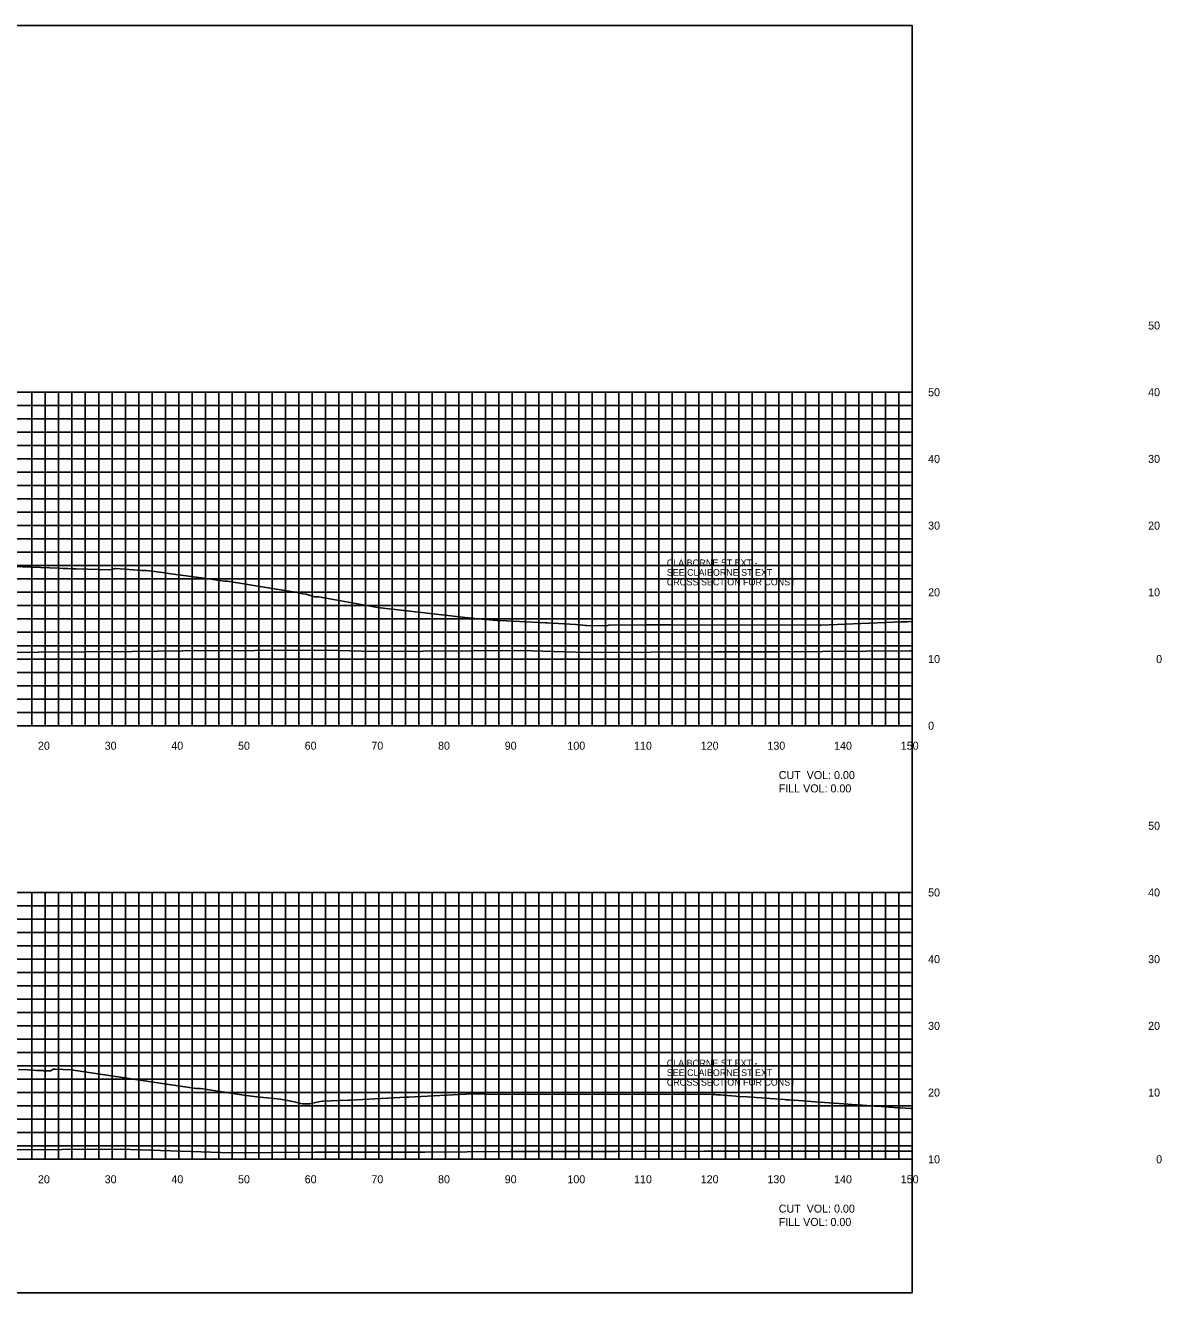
# Model space of a CAD drawing. Extents: x 1797305 to 1804485, y 245831 to 250849.
# Drawn here: x 1803328 to 1803498.4, y 250079.4 to 250269.4 of the extents above; entities that cross this region are included whole.
import ezdxf

# ---------------------------------------------------------------- set-up
doc = ezdxf.new("R2010")
doc.units = 0
for name, color, linetype in [('10', 7, 'Continuous'), ('29', 7, 'Continuous'), ('60', 7, 'Continuous'), ('CL-CNST', 7, 'Continuous'), ('EDPV-LINE', 7, 'Continuous'), ('Level 31', 7, 'Continuous'), ('LIMT-CSLINE', 7, 'Continuous'), ('M-ROADS', 7, 'Continuous')]:
    doc.layers.add(name, color=color, linetype=linetype)

msp = doc.modelspace()

# ---------------------------------------------------------------- linework, layer by layer
msp.add_lwpolyline([(1803161, 250079.43), (1803461, 250079.43), (1803461, 250269.43), (1803161, 250269.43)], close=True)
at = {"layer": '29'}
for p, q in [((1803161, 250214.43), (1803461, 250214.43)), ((1803329, 250164.43), (1803329, 250214.43)), ((1803331, 250164.43), (1803331, 250214.43)), ((1803333, 250164.43), (1803333, 250214.43)), ((1803335, 250164.43), (1803335, 250214.43)), ((1803337, 250164.43), (1803337, 250214.43)), ((1803339, 250164.43), (1803339, 250214.43)), ((1803341, 250164.43), (1803341, 250214.43)), ((1803343, 250164.43), (1803343, 250214.43)), ((1803345, 250164.43), (1803345, 250214.43)), ((1803347, 250164.43), (1803347, 250214.43)), ((1803349, 250164.43), (1803349, 250214.43)), ((1803351, 250164.43), (1803351, 250214.43)), ((1803353, 250164.43), (1803353, 250214.43)), ((1803355, 250164.43), (1803355, 250214.43)), ((1803357, 250164.43), (1803357, 250214.43)), ((1803359, 250164.43), (1803359, 250214.43)), ((1803361, 250164.43), (1803361, 250214.43)), ((1803363, 250164.43), (1803363, 250214.43)), ((1803365, 250164.43), (1803365, 250214.43)), ((1803367, 250164.43), (1803367, 250214.43)), ((1803369, 250164.43), (1803369, 250214.43)), ((1803371, 250164.43), (1803371, 250214.43)), ((1803373, 250164.43), (1803373, 250214.43)), ((1803375, 250164.43), (1803375, 250214.43)), ((1803377, 250164.43), (1803377, 250214.43)), ((1803379, 250164.43), (1803379, 250214.43)), ((1803381, 250164.43), (1803381, 250214.43)), ((1803383, 250164.43), (1803383, 250214.43)), ((1803385, 250164.43), (1803385, 250214.43)), ((1803387, 250164.43), (1803387, 250214.43)), ((1803389, 250164.43), (1803389, 250214.43)), ((1803391, 250164.43), (1803391, 250214.43)), ((1803393, 250164.43), (1803393, 250214.43)), ((1803395, 250164.43), (1803395, 250214.43)), ((1803397, 250164.43), (1803397, 250214.43)), ((1803399, 250164.43), (1803399, 250214.43)), ((1803401, 250164.43), (1803401, 250214.43)), ((1803403, 250164.43), (1803403, 250214.43)), ((1803405, 250164.43), (1803405, 250214.43)), ((1803407, 250164.43), (1803407, 250214.43)), ((1803409, 250164.43), (1803409, 250214.43)), ((1803411, 250164.43), (1803411, 250214.43)), ((1803413, 250164.43), (1803413, 250214.43)), ((1803415, 250164.43), (1803415, 250214.43)), ((1803417, 250164.43), (1803417, 250214.43)), ((1803419, 250164.43), (1803419, 250214.43)), ((1803421, 250164.43), (1803421, 250214.43)), ((1803423, 250164.43), (1803423, 250214.43)), ((1803425, 250164.43), (1803425, 250214.43)), ((1803427, 250164.43), (1803427, 250214.43)), ((1803429, 250164.43), (1803429, 250214.43)), ((1803431, 250164.43), (1803431, 250214.43)), ((1803433, 250164.43), (1803433, 250214.43)), ((1803435, 250164.43), (1803435, 250214.43)), ((1803437, 250164.43), (1803437, 250214.43)), ((1803439, 250164.43), (1803439, 250214.43)), ((1803441, 250164.43), (1803441, 250214.43)), ((1803443, 250164.43), (1803443, 250214.43)), ((1803445, 250164.43), (1803445, 250214.43)), ((1803447, 250164.43), (1803447, 250214.43)), ((1803449, 250164.43), (1803449, 250214.43)), ((1803451, 250164.43), (1803451, 250214.43)), ((1803453, 250164.43), (1803453, 250214.43)), ((1803455, 250164.43), (1803455, 250214.43)), ((1803457, 250164.43), (1803457, 250214.43)), ((1803459, 250164.43), (1803459, 250214.43)), ((1803461, 250164.43), (1803461, 250214.43)), ((1803161, 250212.43), (1803461, 250212.43)), ((1803161, 250210.43), (1803461, 250210.43)), ((1803161, 250208.43), (1803461, 250208.43)), ((1803161, 250206.43), (1803461, 250206.43)), ((1803161, 250204.43), (1803461, 250204.43)), ((1803161, 250202.43), (1803461, 250202.43)), ((1803161, 250200.43), (1803461, 250200.43)), ((1803161, 250198.43), (1803461, 250198.43)), ((1803161, 250196.43), (1803461, 250196.43)), ((1803161, 250194.43), (1803461, 250194.43)), ((1803161, 250192.43), (1803461, 250192.43)), ((1803161, 250190.43), (1803461, 250190.43)), ((1803161, 250188.43), (1803461, 250188.43)), ((1803161, 250186.43), (1803461, 250186.43)), ((1803161, 250184.43), (1803461, 250184.43)), ((1803161, 250182.43), (1803461, 250182.43)), ((1803161, 250180.43), (1803461, 250180.43)), ((1803161, 250178.43), (1803461, 250178.43)), ((1803161, 250176.43), (1803461, 250176.43)), ((1803161, 250174.43), (1803461, 250174.43)), ((1803161, 250172.43), (1803461, 250172.43)), ((1803161, 250170.43), (1803461, 250170.43)), ((1803161, 250168.43), (1803461, 250168.43)), ((1803161, 250166.43), (1803461, 250166.43)), ((1803161, 250164.43), (1803461, 250164.43)), ((1803161, 250139.43), (1803461, 250139.43)), ((1803329, 250099.43), (1803329, 250139.43)), ((1803331, 250099.43), (1803331, 250139.43)), ((1803333, 250099.43), (1803333, 250139.43)), ((1803335, 250099.43), (1803335, 250139.43)), ((1803337, 250099.43), (1803337, 250139.43)), ((1803339, 250099.43), (1803339, 250139.43)), ((1803341, 250099.43), (1803341, 250139.43)), ((1803343, 250099.43), (1803343, 250139.43)), ((1803345, 250099.43), (1803345, 250139.43)), ((1803347, 250099.43), (1803347, 250139.43)), ((1803349, 250099.43), (1803349, 250139.43)), ((1803351, 250099.43), (1803351, 250139.43)), ((1803353, 250099.43), (1803353, 250139.43)), ((1803355, 250099.43), (1803355, 250139.43)), ((1803357, 250099.43), (1803357, 250139.43)), ((1803359, 250099.43), (1803359, 250139.43)), ((1803361, 250099.43), (1803361, 250139.43)), ((1803363, 250099.43), (1803363, 250139.43)), ((1803365, 250099.43), (1803365, 250139.43)), ((1803367, 250099.43), (1803367, 250139.43)), ((1803369, 250099.43), (1803369, 250139.43)), ((1803371, 250099.43), (1803371, 250139.43)), ((1803373, 250099.43), (1803373, 250139.43)), ((1803375, 250099.43), (1803375, 250139.43)), ((1803377, 250099.43), (1803377, 250139.43)), ((1803379, 250099.43), (1803379, 250139.43)), ((1803381, 250099.43), (1803381, 250139.43)), ((1803383, 250099.43), (1803383, 250139.43)), ((1803385, 250099.43), (1803385, 250139.43)), ((1803387, 250099.43), (1803387, 250139.43)), ((1803389, 250099.43), (1803389, 250139.43)), ((1803391, 250099.43), (1803391, 250139.43)), ((1803393, 250099.43), (1803393, 250139.43)), ((1803395, 250099.43), (1803395, 250139.43)), ((1803397, 250099.43), (1803397, 250139.43)), ((1803399, 250099.43), (1803399, 250139.43)), ((1803401, 250099.43), (1803401, 250139.43)), ((1803403, 250099.43), (1803403, 250139.43)), ((1803405, 250099.43), (1803405, 250139.43)), ((1803407, 250099.43), (1803407, 250139.43)), ((1803409, 250099.43), (1803409, 250139.43)), ((1803411, 250099.43), (1803411, 250139.43)), ((1803413, 250099.43), (1803413, 250139.43)), ((1803415, 250099.43), (1803415, 250139.43)), ((1803417, 250099.43), (1803417, 250139.43)), ((1803419, 250099.43), (1803419, 250139.43)), ((1803421, 250099.43), (1803421, 250139.43)), ((1803423, 250099.43), (1803423, 250139.43)), ((1803425, 250099.43), (1803425, 250139.43)), ((1803427, 250099.43), (1803427, 250139.43)), ((1803429, 250099.43), (1803429, 250139.43)), ((1803431, 250099.43), (1803431, 250139.43)), ((1803433, 250099.43), (1803433, 250139.43)), ((1803435, 250099.43), (1803435, 250139.43)), ((1803437, 250099.43), (1803437, 250139.43)), ((1803439, 250099.43), (1803439, 250139.43)), ((1803441, 250099.43), (1803441, 250139.43)), ((1803443, 250099.43), (1803443, 250139.43)), ((1803445, 250099.43), (1803445, 250139.43)), ((1803447, 250099.43), (1803447, 250139.43)), ((1803449, 250099.43), (1803449, 250139.43)), ((1803451, 250099.43), (1803451, 250139.43)), ((1803453, 250099.43), (1803453, 250139.43)), ((1803455, 250099.43), (1803455, 250139.43)), ((1803457, 250099.43), (1803457, 250139.43)), ((1803459, 250099.43), (1803459, 250139.43)), ((1803461, 250099.43), (1803461, 250139.43)), ((1803161, 250137.43), (1803461, 250137.43)), ((1803161, 250135.43), (1803461, 250135.43)), ((1803161, 250133.43), (1803461, 250133.43)), ((1803161, 250131.43), (1803461, 250131.43)), ((1803161, 250129.43), (1803461, 250129.43)), ((1803161, 250127.43), (1803461, 250127.43)), ((1803161, 250125.43), (1803461, 250125.43)), ((1803161, 250123.43), (1803461, 250123.43)), ((1803161, 250121.43), (1803461, 250121.43)), ((1803161, 250119.43), (1803461, 250119.43)), ((1803161, 250117.43), (1803461, 250117.43)), ((1803161, 250115.43), (1803461, 250115.43)), ((1803161, 250113.43), (1803461, 250113.43)), ((1803161, 250111.43), (1803461, 250111.43)), ((1803161, 250109.43), (1803461, 250109.43)), ((1803161, 250107.43), (1803461, 250107.43)), ((1803161, 250105.43), (1803461, 250105.43)), ((1803161, 250103.43), (1803461, 250103.43)), ((1803161, 250101.43), (1803461, 250101.43)), ((1803161, 250099.43), (1803461, 250099.43))]:
    msp.add_line(p, q, dxfattribs=at)
at = {"layer": 'CL-CNST'}
for points in [[(1803161, 250175.43), (1803169.05, 250175.38), (1803183.05, 250175.39), (1803198.21, 250175.28), (1803214.17, 250175.32), (1803227.37, 250175.28), (1803245.01, 250175.35), (1803256.53, 250175.36), (1803275.61, 250175.45), (1803285.69, 250175.28), (1803306.02, 250175.39), (1803314.85, 250175.47), (1803322.91, 250175.42), (1803344, 250175.54), (1803351.63, 250175.66), (1803373.16, 250175.77), (1803380.31, 250175.58), (1803402.32, 250175.72), (1803412.2, 250175.39), (1803431.48, 250175.52), (1803440.95, 250175.52), (1803460.64, 250175.64), (1803461, 250175.64)], [(1803161, 250100.79), (1803167.34, 250100.77), (1803179.55, 250100.82), (1803196.5, 250100.83), (1803210.52, 250100.9), (1803225.66, 250100.64), (1803241.27, 250100.73), (1803254.82, 250100.86), (1803267.21, 250100.78), (1803283.97, 250100.87), (1803295.99, 250101.06), (1803313.13, 250101.15), (1803324.73, 250100.85), (1803342.29, 250100.95), (1803358.84, 250100.4), (1803371.45, 250100.49), (1803387.93, 250100.49), (1803400.61, 250100.57), (1803416.68, 250100.57), (1803429.77, 250100.62), (1803444.97, 250100.63), (1803458.93, 250100.66), (1803461, 250100.66)]]:
    msp.add_lwpolyline(points, dxfattribs=at)
at = {"layer": 'Level 31'}
for p, q in [((1803461, 250164.43), (1803461, 250214.43)), ((1803461.06, 250214.43), (1803461, 250214.43)), ((1803461.06, 250204.43), (1803461, 250204.43)), ((1803461.06, 250194.43), (1803461, 250194.43)), ((1803461.06, 250184.43), (1803461, 250184.43)), ((1803461.06, 250174.43), (1803461, 250174.43)), ((1803161, 250164.43), (1803461, 250164.43)), ((1803331, 250164.37), (1803331, 250164.43)), ((1803341, 250164.37), (1803341, 250164.43)), ((1803351, 250164.37), (1803351, 250164.43)), ((1803361, 250164.37), (1803361, 250164.43)), ((1803371, 250164.37), (1803371, 250164.43)), ((1803381, 250164.37), (1803381, 250164.43)), ((1803391, 250164.37), (1803391, 250164.43)), ((1803401, 250164.37), (1803401, 250164.43)), ((1803411, 250164.37), (1803411, 250164.43)), ((1803421, 250164.37), (1803421, 250164.43)), ((1803431, 250164.37), (1803431, 250164.43)), ((1803441, 250164.37), (1803441, 250164.43)), ((1803451, 250164.37), (1803451, 250164.43)), ((1803461, 250164.37), (1803461, 250164.43)), ((1803461.06, 250164.43), (1803461, 250164.43)), ((1803461, 250099.43), (1803461, 250139.43)), ((1803461.06, 250139.43), (1803461, 250139.43)), ((1803461.06, 250129.43), (1803461, 250129.43)), ((1803461.06, 250119.43), (1803461, 250119.43)), ((1803461.06, 250109.43), (1803461, 250109.43)), ((1803161, 250099.43), (1803461, 250099.43)), ((1803331, 250099.37), (1803331, 250099.43)), ((1803341, 250099.37), (1803341, 250099.43)), ((1803351, 250099.37), (1803351, 250099.43)), ((1803361, 250099.37), (1803361, 250099.43)), ((1803371, 250099.37), (1803371, 250099.43)), ((1803381, 250099.37), (1803381, 250099.43)), ((1803391, 250099.37), (1803391, 250099.43)), ((1803401, 250099.37), (1803401, 250099.43)), ((1803411, 250099.37), (1803411, 250099.43)), ((1803421, 250099.37), (1803421, 250099.43)), ((1803431, 250099.37), (1803431, 250099.43)), ((1803441, 250099.37), (1803441, 250099.43)), ((1803451, 250099.37), (1803451, 250099.43)), ((1803461, 250099.37), (1803461, 250099.43)), ((1803461.06, 250099.43), (1803461, 250099.43))]:
    msp.add_line(p, q, dxfattribs=at)
at = {"layer": 'M-ROADS'}
for points in [[(1803323.61, 250188.39), (1803332.94, 250188.03), (1803333.62, 250188.01), (1803334.39, 250187.98), (1803335.07, 250187.96), (1803335.32, 250187.95), (1803335.61, 250187.94), (1803340.79, 250187.79), (1803341.53, 250187.98), (1803341.58, 250187.98), (1803343.5, 250187.85), (1803345.45, 250187.7), (1803345.6, 250187.71), (1803345.68, 250187.71), (1803345.71, 250187.71), (1803346.17, 250187.71), (1803348.58, 250187.38), (1803348.87, 250187.34), (1803349.82, 250187.2), (1803355.54, 250186.47), (1803357.89, 250186.11), (1803358.3, 250186.11), (1803367.19, 250184.64), (1803368.81, 250184.38), (1803368.84, 250184.38), (1803368.98, 250184.35), (1803369.57, 250184.21), (1803370.1, 250184.16), (1803371.39, 250183.76), (1803371.55, 250183.76), (1803371.75, 250183.76), (1803371.89, 250183.76), (1803372.02, 250183.74), (1803372.03, 250183.74), (1803380.84, 250182.15), (1803394.87, 250180.53), (1803398.74, 250180.18), (1803398.87, 250180.18), (1803399.24, 250180.18), (1803406.03, 250179.85), (1803406.28, 250179.83), (1803410.52, 250179.58), (1803410.62, 250179.58), (1803411.24, 250179.54), (1803412.02, 250179.43), (1803412.18, 250179.43), (1803415.1, 250179.39), (1803415.18, 250179.39), (1803415.53, 250179.49), (1803421.09, 250179.53), (1803422.14, 250179.55), (1803422.19, 250179.55), (1803424.79, 250179.56), (1803447.22, 250179.48), (1803447.38, 250179.48), (1803459.34, 250179.99), (1803460.29, 250180.02), (1803461, 250180.07)], [(1803326.97, 250112.9), (1803328.41, 250112.83), (1803329.2, 250112.79), (1803329.7, 250112.76), (1803330.04, 250112.74), (1803330.29, 250112.73), (1803330.38, 250112.72), (1803330.49, 250112.72), (1803330.65, 250112.72), (1803330.78, 250112.71), (1803330.88, 250112.71), (1803330.97, 250112.71), (1803331.05, 250112.7), (1803331.12, 250112.7), (1803331.17, 250112.7), (1803331.22, 250112.7), (1803331.27, 250112.7), (1803331.31, 250112.7), (1803331.34, 250112.69), (1803331.38, 250112.69), (1803331.41, 250112.69), (1803331.43, 250112.69), (1803331.46, 250112.69), (1803331.79, 250112.67), (1803331.83, 250112.69), (1803332.18, 250112.93), (1803332.5, 250112.93), (1803334.89, 250112.83), (1803349.86, 250110.59), (1803352.96, 250110.15), (1803353.61, 250110.05), (1803353.62, 250110.05), (1803353.74, 250110.03), (1803354.25, 250110.03), (1803354.25, 250110.03), (1803361.14, 250108.98), (1803362.73, 250108.78), (1803366.29, 250108.42), (1803366.5, 250108.4), (1803367.81, 250108.12), (1803367.86, 250108.12), (1803369.37, 250107.79), (1803369.58, 250107.75), (1803369.79, 250107.73), (1803369.86, 250107.73), (1803370.27, 250107.74), (1803370.31, 250107.73), (1803370.64, 250107.74), (1803370.82, 250107.77), (1803372.04, 250108.06), (1803372.56, 250108.12), (1803376.53, 250108.29), (1803376.74, 250108.28), (1803385.12, 250108.75), (1803385.45, 250108.75), (1803395.01, 250109.22), (1803395.66, 250109.22), (1803395.67, 250109.22), (1803395.89, 250109.23), (1803396.37, 250109.23), (1803396.89, 250109.21), (1803431.1, 250109.15), (1803431.15, 250109.15), (1803431.29, 250109.14), (1803431.46, 250109.13), (1803431.67, 250109.11), (1803431.93, 250109.09), (1803432.27, 250109.07), (1803432.71, 250109.04), (1803433.32, 250108.99), (1803435.16, 250108.86), (1803436.26, 250108.78), (1803437.62, 250108.68), (1803439.2, 250108.57), (1803439.68, 250108.53), (1803441.86, 250108.38), (1803442.13, 250108.36), (1803442.54, 250108.33), (1803444.65, 250108.18), (1803445.06, 250108.15), (1803445.14, 250108.14), (1803447.88, 250107.94), (1803447.9, 250107.94), (1803448.58, 250107.89), (1803450.71, 250107.73), (1803452.01, 250107.64), (1803453.54, 250107.53), (1803455.44, 250107.4), (1803456.37, 250107.33), (1803458.87, 250107.16), (1803459.2, 250107.14), (1803460.74, 250107.04), (1803461, 250107.03)]]:
    msp.add_lwpolyline(points, dxfattribs=at)

# ---------------------------------------------------------------- texts
at = {"layer": '10'}
for s, p in [('20', (1803329.9, 250160.83)), ('30', (1803339.9, 250160.83)), ('40', (1803349.9, 250160.83)), ('50', (1803359.9, 250160.83)), ('60', (1803369.9, 250160.83)), ('70', (1803379.9, 250160.83)), ('80', (1803389.9, 250160.83)), ('90', (1803399.9, 250160.83)), ('100', (1803409.3, 250160.83)), ('110', (1803419.3, 250160.83)), ('120', (1803429.3, 250160.83)), ('130', (1803439.3, 250160.83)), ('140', (1803449.3, 250160.83)), ('150', (1803459.3, 250160.83)), ('20', (1803329.9, 250095.83)), ('30', (1803339.9, 250095.83)), ('40', (1803349.9, 250095.83)), ('50', (1803359.9, 250095.83)), ('60', (1803369.9, 250095.83)), ('70', (1803379.9, 250095.83)), ('80', (1803389.9, 250095.83)), ('90', (1803399.9, 250095.83)), ('100', (1803409.3, 250095.83)), ('110', (1803419.3, 250095.83)), ('120', (1803429.3, 250095.83)), ('130', (1803439.3, 250095.83)), ('140', (1803449.3, 250095.83)), ('150', (1803459.3, 250095.83))]:
    msp.add_text(s, height=1.2, dxfattribs=at).set_placement(p)
at = {"layer": '60'}
for s, p in [('50', (1803496.4, 250223.83)), ('50', (1803463.4, 250213.83)), ('40', (1803496.4, 250213.83)), ('40', (1803463.4, 250203.83)), ('30', (1803496.4, 250203.83)), ('30', (1803463.4, 250193.83)), ('20', (1803496.4, 250193.83)), ('20', (1803463.4, 250183.83)), ('10', (1803496.4, 250183.83)), ('10', (1803463.4, 250173.83)), ('0', (1803497.6, 250173.83)), ('0', (1803463.4, 250163.83)), ('50', (1803496.4, 250148.83)), ('50', (1803463.4, 250138.83)), ('40', (1803496.4, 250138.83)), ('40', (1803463.4, 250128.83)), ('30', (1803496.4, 250128.83)), ('30', (1803463.4, 250118.83)), ('20', (1803496.4, 250118.83)), ('20', (1803463.4, 250108.83)), ('10', (1803496.4, 250108.83)), ('10', (1803463.4, 250098.83)), ('0', (1803497.6, 250098.83))]:
    msp.add_text(s, height=1.2, dxfattribs=at).set_placement(p)
at = {"layer": 'EDPV-LINE'}
for s, p in [('CUT  VOL: 0.00', (1803441, 250156.43)), ('FILL VOL: 0.00', (1803441, 250154.43)), ('CUT  VOL: 0.00', (1803441, 250091.43)), ('FILL VOL: 0.00', (1803441, 250089.43))]:
    msp.add_text(s, height=1.2, dxfattribs=at).set_placement(p)
at = {"layer": 'LIMT-CSLINE'}
for s, p in [('CLAIBORNE ST EXT -', (1803424.21, 250188.35)), ('SEE CLAIBORNE ST EXT', (1803424.21, 250186.91)), ('CROSS SECTION FOR CONST ', (1803424.21, 250185.47)), ('CLAIBORNE ST EXT -', (1803424.21, 250113.35)), ('SEE CLAIBORNE ST EXT', (1803424.21, 250111.91)), ('CROSS SECTION FOR CONST ', (1803424.21, 250110.47))]:
    msp.add_text(s, height=1, dxfattribs=at).set_placement(p)

doc.saveas('drawing.dxf')
